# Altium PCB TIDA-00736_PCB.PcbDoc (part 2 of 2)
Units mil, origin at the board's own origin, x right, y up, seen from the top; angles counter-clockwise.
Board outline 3346.46 x 1968.5 mil, 2 copper layers (Top Layer, Bottom Layer), stack 62 mil thick; 81 components, 63 nets, 308 pads, 545 vias.
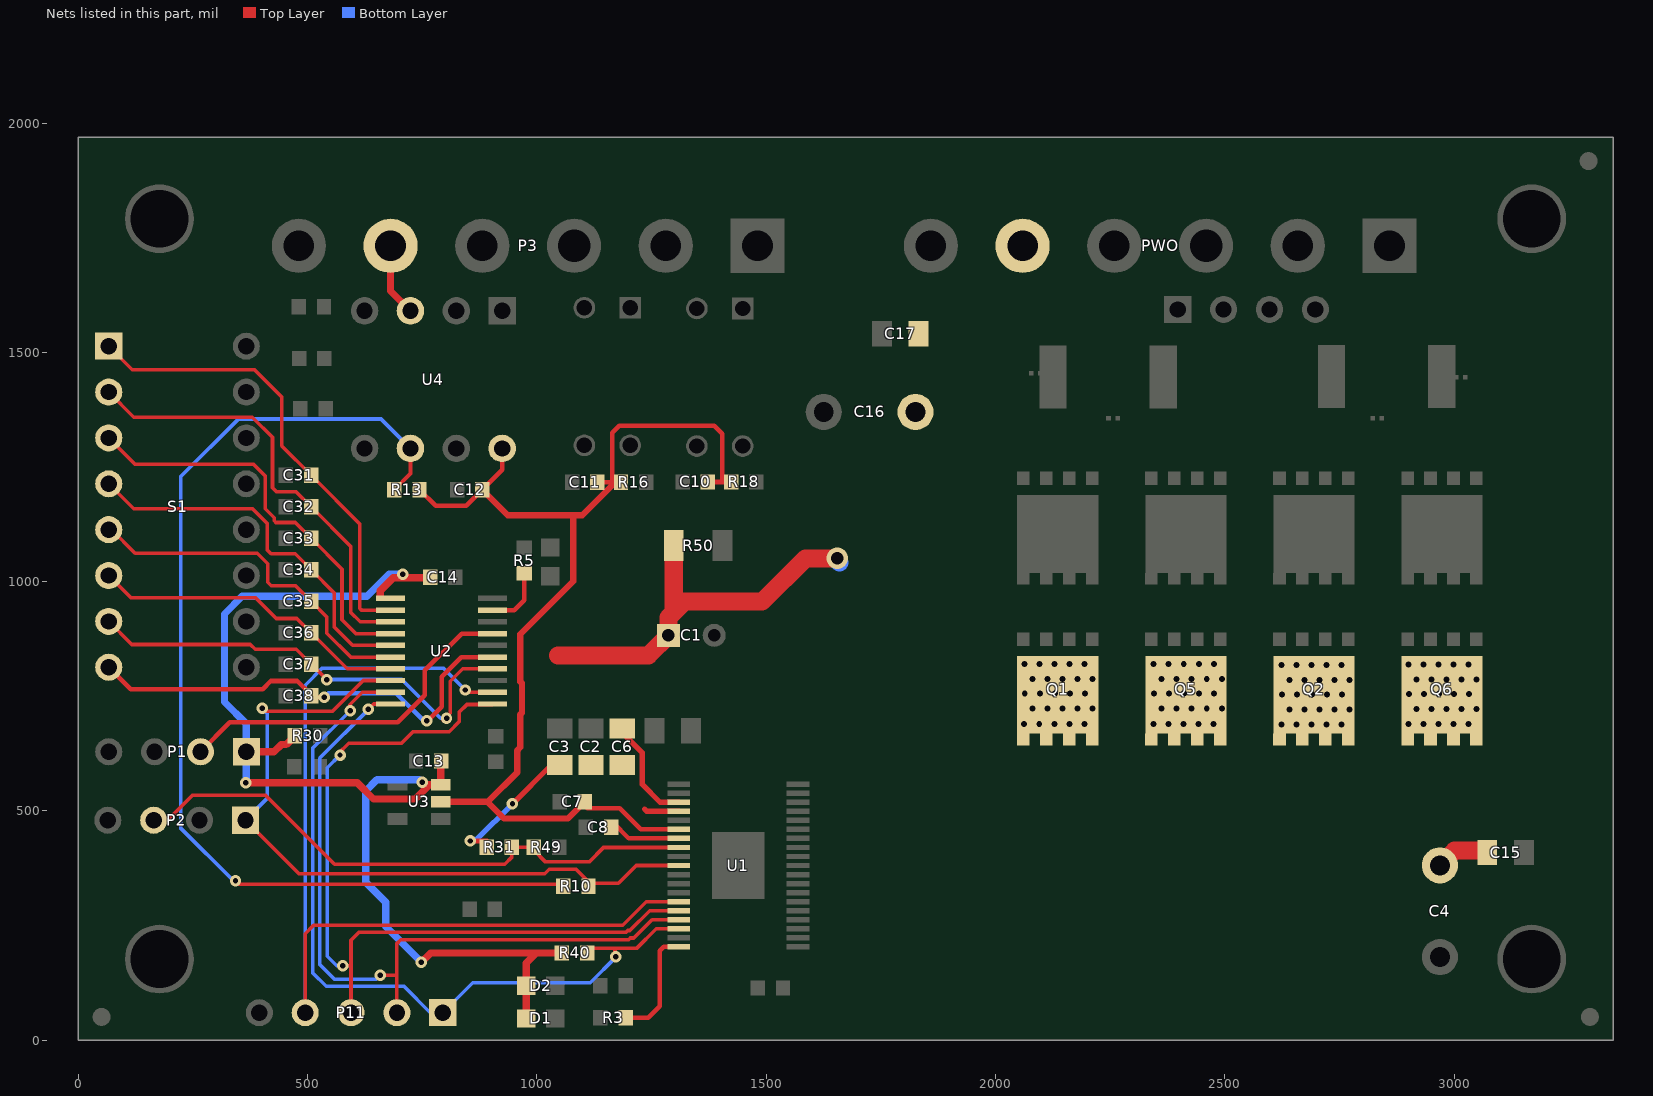
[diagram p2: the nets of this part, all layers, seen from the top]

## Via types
v1: diameter 19.68, hole 13, Top Layer to Bottom Layer, 434 vias
v2: diameter 25, hole 13, Top Layer to Bottom Layer, 54 vias
v3: diameter 25, hole 11.81, Top Layer to Bottom Layer, 17 vias
v4: diameter 25, hole 12, Top Layer to Bottom Layer, 16 vias
v5: diameter 25, hole 15.75, Top Layer to Bottom Layer, 16 vias
v6: diameter 19.68, hole 11.81, Top Layer to Bottom Layer, 7 vias
v7: diameter 47.24, hole 27.56, Top Layer to Bottom Layer, 1 vias

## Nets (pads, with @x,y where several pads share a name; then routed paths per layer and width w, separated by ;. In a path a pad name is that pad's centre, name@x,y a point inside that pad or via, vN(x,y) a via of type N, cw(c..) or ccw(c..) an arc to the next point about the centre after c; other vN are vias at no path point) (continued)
REG3P3: C13.2 C14.2 D1.1 D2.1 P1.1 R30.1 R40.1 U2.1 U3.3 | length 2623.8
  Top Layer w15.75: v4(365.75,561.42) 608.27,561.42 643.7,525.98 734.65,525.98 766.14,557.48 ; P1.1@366.54,629.13 426.92,629.13 442.47,644.69 453.35,644.69 R30.1@472.44,663.78 ; 658.66,970.08 658.66,980.32 687.01,1008.66 766.14,1008.66 C14.2@767.32,1009.84 ; v4(748.43,170.47) 768.5,190.55 999.21,190.55 ; v4(750,562.21) 754.72,557.48 766.14,557.48 ; U3.3@771.26,557.48 766.14,557.48 ; C13.2@790.55,614.57 U3.3@790.55,557.48 766.14,557.48 ; D1.1@977.07,47.74 D2.1@977.07,119 977.07,168.41 999.21,190.55 ; R40.1@1054.72,190.55 999.21,190.55
  Bottom Layer w15.75: v4(365.75,561.42) 366.54,562.21 P1.1@366.54,629.13 366.54,690.16 318.9,737.8 318.9,929.78 357.23,968.11 629.53,968.11 678.35,1016.93 706.3,1016.93 v4(707.48,1015.75) ; v4(748.43,170.47) 670.47,248.43 670.47,301.18 626.77,344.88 626.77,543.7 651.18,568.11 744.1,568.11 v4(750,562.21)
S1: C31.2 S1.1 U2.2 | length 1023.1
  Top Layer w8: S1.1@66.54,1513.39 117.72,1462.21 384.25,1462.21 443.7,1402.76 443.7,1296.06 C31.2@507.87,1231.89 613.78,1125.98 613.78,941.73 617.52,937.99 U2.2@680.91,937.99
S2: C32.2 S1.2 U2.3 | length 970.7
  Top Layer w7.87: S1.2@66.54,1413.39 121.26,1358.66 379.72,1358.66 423.62,1314.76 423.62,1204.73 431.89,1196.46 474.63,1196.46 C32.2@507.87,1163.22 594.49,1076.6 594.49,932.68 614.76,912.4 U2.3@680.91,912.4
S3: C33.2 S1.3 U2.4 | length 901.4
  Top Layer w7.87: S1.3@66.54,1313.39 123.62,1256.3 382.08,1256.3 407.87,1230.51 407.87,1158.92 427.56,1139.23 427.56,1132.68 431.1,1129.13 473.28,1129.13 C33.2@507.87,1094.54 575.2,1027.22 575.2,916.93 605.32,886.81 U2.4@680.91,886.81
S4: C34.2 S1.4 U2.5 | length 837.7
  Top Layer w7.87: S1.4@66.54,1213.39 120.87,1159.06 379.92,1159.06 411.81,1127.17 411.81,1069.29 420.47,1060.63 473.12,1060.63 C34.2@507.87,1025.87 558.27,975.48 558.27,901.18 598.23,861.22 U2.5@680.91,861.22
S5: C35.2 S1.5 U2.6 | length 773.8
  Top Layer w7.87: S1.5@66.54,1113.39 72.84,1113.39 124.02,1062.21 390.16,1062.21 413.39,1038.98 413.39,998.82 420.87,991.34 473.73,991.34 C35.2@507.87,957.2 542.13,922.95 542.13,887.4 593.9,835.63 U2.6@680.91,835.63
S6: C36.2 S1.6 U2.7 | length 698.6
  Top Layer w7.87: S1.6@66.54,1013.39 115.35,964.57 387.01,964.57 431.89,919.69 476.72,919.69 C36.2@507.87,888.53 586.36,810.04 U2.7@680.91,810.04
S7: C37.2 S1.7 U2.14 | length 1029.9
  Top Layer w7.87: S1.7@66.54,913.39 116.93,862.99 375.39,862.99 386.02,852.36 475.37,852.36 C37.2@507.87,819.85 508.49,819.85 v4(541.73,786.61) ; v4(803,702) 801.22,702 795.67,696.45 795.67,698.03 811.02,713.39 811.02,782.68 838.39,810.04 U2.14@903.35,810.04
  Bottom Layer w7.87: v4(541.73,786.61) 705.51,786.61 790.12,702 v4(803,702)
S8: C38.2 S1.8 U2.15 | length 1004.6
  Top Layer w10: S1.8@66.54,813.39 114.17,765.75 401.97,765.75 419.69,783.47 477.95,783.47 507.87,753.54 C38.2@507.87,751.18 511.42,747.64 v4(536.22,747.64) ; v4(760,697) 761.96,697 792.52,727.56 792.52,792.91 835.24,835.63 U2.15@903.35,835.63
  Bottom Layer w10: v4(536.22,747.64) 545.67,757.09 692.91,757.09 753,697 v4(760,697)
SCLK: P11.4 U1.14 U2.12 | length 2175
  Top Layer w7.87: P11.4@494.88,60.24 494.88,232.68 513.2,251 1187.22,251 1238.58,302.36 U1.14@1309.45,302.36 ; v3(843.7,763.78) 848.62,758.86 U2.12@903.35,758.86
  Bottom Layer w7.87: P11.4@494.88,60.24 494.88,774.15 531.66,810.93 796.56,810.93 v3(843.7,763.78)
SCS: P11.2 U1.16 U2.10 | length 1625.1
  Top Layer w7.87: v4(632.87,721.46) 644.69,733.27 U2.10@680.91,733.27 ; v4(658.66,142.13) 694.1,142.13 694.88,141.34 ; P11.2@694.88,60.24 694.88,141.34 ; U1.16@1309.45,262.99 1251.18,262.99 1211.19,223 1203.76,223 1200.27,219.5 703.36,219.5 694.88,211.02 694.88,141.34
  Bottom Layer w7.87: v4(632.87,721.46) 526.77,615.35 526.77,165.35 558.66,133.47 650,133.47 v4(658.66,142.13)
SDATAO: P11.1 R40.2 U1.17 U2.9 | length 1705
  Top Layer w7.87: v3(593.31,718.9) 590.95,721.26 590.95,724.8 592.13,725.98 592.13,731.89 619.09,758.86 U2.9@680.91,758.86 ; R40.2@1110.24,202.68 1112.52,200.39 1170.47,200.39 ; v3(1172.44,181.89) 1170.47,183.86 1170.47,200.39 ; U1.17@1309.45,243.31 1260.24,243.31 1217.32,200.39 1170.47,200.39
  Bottom Layer w7.87: v3(593.31,718.9) 511.02,636.61 511.02,147.64 540.95,117.72 710.24,117.72 767.72,60.24 P11.1@794.88,60.24 860.24,125.59 1116.14,125.59 v3(1172.44,181.89)
SDATI: P11.3 U1.15 U2.11 | length 1810
  Top Layer w7.87: v3(570.87,622.05) 568.9,622.05 566.54,624.41 590.16,648.03 705.03,648.03 730,673 749.62,673 749.93,672.69 770.07,672.69 770.38,673 808.96,673 831.1,695.15 831.1,715.75 847.64,732.28 902.36,732.28 U2.11@903.35,733.27 ; v3(577.17,162.6) 594.88,162.6 ; P11.3@594.88,60.24 594.88,162.6 ; U1.15@1309.45,282.68 1246.06,282.68 1202.76,239.37 1197.86,239.37 1193.74,235.25 611.63,235.25 594.88,218.5 594.88,162.6
  Bottom Layer w7.87: v3(570.87,622.05) 542.91,594.09 542.91,183.07 563.39,162.6 v3(577.17,162.6)
SLEEPN: P2.3 R31.2 R49.1 U1.8 | length 1287.4
  Top Layer w8: P2.3@164.57,479.92 194.47,479.92 248.55,534 409,534 559,384 930,384 945.56,399.56 R31.2@945.56,421 R49.1@993.44,421 993.44,414.56 1019,389 1114,389 1145.47,420.47 U1.8@1309.45,420.47
STALLN: R3.1 U1.19 | length 250.6
  Top Layer w10: R3.1@1193.7,49.21 1242.91,49.21 1268.11,74.41 1268.11,195.28 1276.77,203.94 U1.19@1309.45,203.94
STATE: R5.2 U2.19 | length 125.4
  Top Layer w10: U2.19@903.35,937.99 950.59,937.99 972.44,959.84 R5.2@972.44,1007.09
STEP_AIN1: P2.1 R10.1 U1.10 U2.8 | length 1610.9
  Top Layer w7.87: P2.1@364.57,479.92 481.49,363 1017,363 1027,373 1085.36,373 1116,342.36 1177.8,342.36 1216.54,381.1 U1.10@1309.45,381.1 ; v4(400.79,724.41) 400,723.62 400,717.32 554.53,717.32 621.65,784.45 U2.8@680.91,784.45
  Bottom Layer w7.87: P2.1@364.57,479.92 411.81,527.17 411.81,713.39 v4(400.79,724.41)
STP: P3.5 U4.3 | length 159.7
  Top Layer w15.75: P3.5@681.1,1732.28 681.1,1633.86 U4.3@724.41,1590.55
STP_ISO: R10.2 R13.2 U4.6 | length 2333.7
  Top Layer w7.87: R13.2@688.98,1200.39 724.41,1235.83 U4.6@724.41,1290.55
  Top Layer w8: v3(342.91,347.64) 350.55,340 R10.2@1055.44,340
  Bottom Layer w7.87: v3(342.91,347.64) 338.39,347.64 223.23,462.8 223.23,1228.54 349.41,1354.72 660.24,1354.72 U4.6@724.41,1290.55
TEST: P1.2 U2.17 | length 775.2
  Top Layer w10: P1.2@266.54,629.13 330.79,693.39 696.63,693.39 755.91,752.66 755.91,806.69 836.02,886.81 U2.17@903.35,886.81
V5: C7.1 C10.2 C11.2 C12.2 R13.1 R16.1 R18.1 U1.6 U3.2 U4.8 | length 2456.8
  Top Layer w10: R13.1@744.1,1200.39 779.13,1165.35 846.06,1165.35 C12.2@881.1,1200.39 924.41,1243.7 U4.8@924.41,1290.55 ; C7.1@1110.24,505.91 1180.71,505.91 1226.77,459.84 U1.6@1309.45,459.84 ; C11.2@1131.89,1216.93 1161.81,1216.93 ; R16.1@1183.46,1216.93 1171.26,1216.93 1164.35,1216.93 ; C10.2@1372.83,1217.32 1403.94,1217.32 ; R18.1@1423.62,1217.32 1403.94,1217.32 ; 1161.81,1216.93 1164.35,1216.93 ; 1161.81,1216.93 1164.35,1214.39 1164.35,1216.93 ; 1164.35,1216.93 1164.35,1324.59 1179.53,1339.76 1387.01,1339.76 1403.94,1322.84 1403.94,1217.32
  Top Layer w13.78: U3.2@790.55,520.08 892.13,520.08 928.74,483.47 1067.72,483.47 C7.1@1104.73,520.47 ; C12.2@881.1,1200.39 936.61,1144.88 1079.53,1144.88 ; 895,522 957,584 957,632 964,639 964,688.61 964,710.36 967.48,713.84 967.48,778.28 964,781.76 964,790.85 964,885.39 1079.53,1000.92 1079.53,1144.88 ; R16.1@1171.26,1216.93 1099.21,1144.88 1079.53,1144.88
VCP: C6.1 U1.3 | length 248
  Top Layer w11.81: C6.1@1174.41,687.24 1174.41,682.28 1229.53,627.17 1229.53,558.41 1269.04,518.9 U1.3@1309.45,518.9
VINT: C8.1 U1.7 | length 156.9
  Top Layer w10: C8.1@1166.54,474.02 1200.39,440.16 U1.7@1309.45,440.16
VM: C1.1 C2.1 C3.1 C4.1 C6.2 C15.2 C16.1 C17.2 PWO.5 Q1.5 Q2.5 Q5.5 Q6.5 R31.1 R50.1 U1.4 | length 1373.5
  Top Layer w11.81: v3(854.72,434.65) R31.1@891.34,434.65 ; v3(946.85,515.75) 1030.87,599.76 C3.1@1054.33,599.76 ; 1234.65,504.33 1239.76,499.21 U1.4@1309.45,499.21
  Top Layer w39.37: 1045.67,839.37 1242.91,839.37 C1.1@1286.61,883.07 1286.61,921.65 1303.15,938.19 ; R50.1@1298.43,1078.74 1298.43,942.91 1303.15,938.19 ; v7(1654.72,1050.79) 1585.43,1050.79 1491.34,956.69 1321.65,956.69 1303.15,938.19 ; C4.1@2968.9,381.5 3001.18,413.78 3001.18,414.17 3067.48,414.17 C15.2@3072.21,409.45
  Bottom Layer w11.81: v3(854.72,434.65) 854.72,435.04 857.09,437.4 868.5,437.4 v3(946.85,515.75)
  Bottom Layer w39.37: v7(1654.72,1050.79) 1654.72,1046.46 v7@1659.45,1041.73
  other v1: 2623.23,688.19 2656.01,688.19 2688.78,688.19 2721.56,688.19 2754.33,688.19 2900,689.37 2932.78,689.37 2965.55,689.37 2998.33,689.37 3031.1,689.37 2062.6,690.16 2095.38,690.16 2128.15,690.16 2160.93,690.16 2193.7,690.16 2344.49,690.16 2377.27,690.16 2410.04,690.16 2442.82,690.16 2475.59,690.16 2640.95,721.26 2673.72,721.26 2706.5,721.26 2739.27,721.26 2772.05,721.26 2917.72,722.44 2950.49,722.44 2983.27,722.44 3016.04,722.44 3048.82,722.44 2080.32,723.23 2113.09,723.23 2145.87,723.23 2178.64,723.23 2211.42,723.23 2362.21,723.23 2394.98,723.23 2427.76,723.23 2460.53,723.23 2493.31,723.23 2624.41,753.94 2657.19,753.94 2689.96,753.94 2722.74,753.94 2755.51,753.94 2063.78,755.91 2096.56,755.91 2129.33,755.91 2162.11,755.91 2194.88,755.91 2345.67,755.91 2378.45,755.91 2411.22,755.91 2444,755.91 2476.77,755.91 2901.18,755.12 2933.96,755.12 2966.73,755.12 2999.51,755.12 3032.28,755.12 2640.95,785.83 2673.72,785.83 2706.5,785.83 2739.27,785.83 2772.05,785.83 2917.72,787.01 2950.49,787.01 2983.27,787.01 3016.04,787.01 3048.82,787.01 2080.32,787.8 2113.09,787.8 2145.87,787.8 2178.64,787.8 2211.42,787.8 2362.21,787.8 2394.98,787.8 2427.76,787.8 2460.53,787.8 2493.31,787.8 2623.62,818.5 2656.4,818.5 2689.17,818.5 2721.95,818.5 2754.72,818.5 2900.39,819.69 2933.17,819.69 2965.95,819.69 2998.72,819.69 3031.5,819.69 2062.99,820.47 2095.77,820.47 2128.54,820.47 2161.32,820.47 2194.1,820.47 2344.88,820.47 2377.66,820.47 2410.43,820.47 2443.21,820.47 2475.98,820.47
pads on no net: FID1.1 FID2.1 FID3.1 U1.12 U1.13 U3.4 U3.5 U4.1 U4.4 U4.7

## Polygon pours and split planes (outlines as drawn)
GND on Top Layer "Bottom Layer-No Net" (solid, remove dead copper, pour order 47): 3,1975 3349.46,1975 3349.46,6.5 3,6.5
VM on Top Layer "Bottom Layer-No Net" (solid, remove dead copper, pour order 43): 998.82,552.76 955.12,484.65 928.74,483.47 886.61,518.9 892.13,652.76 952.36,712.99 952.36,873.75 1079.53,1000.92 1326.77,1001.18 1326.77,826.77 1169.69,777.17 1030.71,777.17 1030.87,599.76
GND on Top Layer "Bottom Layer-No Net" (solid, remove dead copper, pour order 41): 1024.8,659.06 1024.8,767.72 1187.4,768.9 1182.68,716.93 1148.43,659.06
VM on Top Layer "Bottom Layer-No Net" (solid, remove dead copper, pour order 37): 1967.32,1798.03 2162.6,1795.67 2018.11,1492.13 1829.53,1308.27 1744.49,1361.02 1852.36,1600 1955.91,1777.17
NetJJ1_2 on Top Layer "Bottom Layer-No Net" (solid, remove dead copper, pour order 23): 2563.78,1539.37 2561.42,1537.01 2245.67,1537.01 2245.67,1360.63 2238.58,1353.54 2237.4,1354.72 1994.1,1354.72 1994.1,1212.21 1996.06,1210.24 1998.82,1207.48 2563.39,1207.48
NetJJ2_2 on Top Layer "Bottom Layer-No Net" (solid, remove dead copper, pour order 21): 2563.78,1208.66 3094.49,1208.66 3094.49,1353.15 3091.73,1355.91 2850.79,1355.91 2850.79,1518.9 2833.86,1535.83 2830.32,1539.37 2563.78,1539.37
BOUT2 on Top Layer "Bottom Layer-No Net" (solid, remove dead copper, pour order 9): 2829.13,1188.98 3138.58,1188.98 3139.37,1189.76 3139.37,857.48 2829.13,857.48
BOUT1 on Top Layer "Bottom Layer-No Net" (solid, remove dead copper, pour order 7): 2574.31,1188.98 2827.17,1188.98 2827.17,857.48 2828.35,856.3 2827.17,857.48 2572.84,857.48
AOUT2 on Top Layer "Bottom Layer-No Net" (solid, remove dead copper, pour order 5): 2274.8,1190.95 2573.13,1190.95 2574.31,1192.13 2574.31,858.66 2279.13,858.66 2275.98,861.81
AOUT1 on Top Layer "Bottom Layer-No Net" (solid, remove dead copper, pour order 3): 1962.99,1189.76 2274.02,1189.76 2274.02,859.84 2272.05,861.81 1962.99,861.81
VM on Top Layer "Bottom Layer-No Net" (solid, remove dead copper, pour order 2): 988.19,622.44 988.58,622.84 1215.35,622.84 1215.35,544.88 1259.45,500.79 1266.14,494.09 1266.54,494.09 1266.54,492.91 1254.33,480.71 1251.18,477.56 1234.25,477.56 1233.07,477.56 1189.76,520.87 1189.37,520.87 1175.98,534.25 1175.59,534.25 1159.84,550 1157.09,552.76 1029.92,552.76 998.82,552.76 988.19,563.39
GND on Bottom Layer "GND" (solid, remove dead copper, pour order 45): 0,1968.5 0,0 3346.46,0 3346.46,1968.5
VM on Bottom Layer "Bottom Layer-No Net" (solid, remove dead copper, pour order 35): 3151.18,572.84 3118.9,370.47 2925.98,285.43 2856.69,340.55 2824.8,471.65 2045.67,556.69 2045.67,575.2
VM on Bottom Layer "Bottom Layer-No Net" (solid, remove dead copper, pour order 33): 1964.96,1807.09 2178.74,1807.09 1981.1,1037.01 2227.17,954.33 2939.76,974.8 3118.9,1066.93 3151.18,1048.43 3151.18,561.42 2045.67,561.42 2024.8,674.02 1866.14,701.58 1721.26,804.72 1638.58,1064.57 1728.35,1448.43
BOUT2 on Bottom Layer "Bottom Layer-No Net" (solid, remove dead copper, pour order 31): 2768.5,1807.48 2931.89,1805.51 3137.01,1059.06 2892.54,932.18 2635.83,1617.32
BOUT1 on Bottom Layer "Bottom Layer-No Net" (solid, remove dead copper, pour order 29): 2551.97,1807.48 2759.06,1811.02 2751.58,1722.05 2664.17,1611.81 2662.21,1556.69 2894.1,927.95 2557.87,941.34
AOUT2 on Bottom Layer "Bottom Layer-No Net" (solid, remove dead copper, pour order 27): 2356.3,1809.45 2540.55,1809.45 2544.49,1636.61 2548.43,943.31 2191.34,929.92
AOUT1 on Bottom Layer "Bottom Layer-No Net" (solid, remove dead copper, pour order 25): 2191.34,1803.54 2193.31,1805.51 2318.5,1805.51 2327.95,1805.51 2331.89,1801.58 2430.71,1615.75 2430.71,1556.69 2175.98,916.54 1951.97,1034.25

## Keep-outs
Keep-Out Layer:
  lines w3.94: 3.15,98.43 103.15,98.43 103.15,-1.57 ; 3243.31,1970.08 3243.31,1870.08 3343.31,1870.08 ; 3248.03,3.15 3248.03,103.15 3348.03,103.15
  lines w6.69: 1112,1003.73 1112,1111 1167.54,1166.54 1497.64,1166.54 1558.27,1227.17 1558.27,1968.5
  lines w8: 0,0 3346.46,0 3346.46,1968.5 0,1968.5 0,0
  text ".Layer_Name" at 295.35,-1258.89 h60

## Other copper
Top Layer:
  text ".Layer_Name" at 295.35,-1258.89 h60
Bottom Layer:
  text ".Layer_Name" at 295.35,-1258.89 h60

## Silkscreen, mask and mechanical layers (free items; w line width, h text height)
Top Overlay:
  text "A+" at 2785.43,1570.47 h31.5
  text "A-" at 2873.49,1570.47 h31.5
  text "B+" at 2961.55,1570.47 h31.5
  text "B-" at 3049.61,1570.47 h31.5
  text "VM+" at 2081.1,1551.18 h31.5 r90
  text ".PCB_Rev" at 3310,1135 h60 r90
  text "SBW" at 179.13,538.98 h31.5
  text ".PRJ_Number" at 3310,535 h60 r90
  text "E  D  S" at 159.84,384.25 h31.5
  text "FAULTn" at 836.22,180.71 h31.5
  text "SI" at 604.33,122.05 h31.5 r45
  text "GD" at 387.01,120.47 h31.5 r45
  text "SC" at 492.13,120.47 h31.5 r45
  text "SS" at 699.61,119.29 h31.5 r45
  text "SO" at 800.79,119.29 h31.5 r45
  text "STALLn" at 1310.24,24.8 h31.5
  text ".Layer_Name" at 295.35,-1258.89 h60
Bottom Overlay:
  text ".Layer_Name" at 295.35,-1258.89 h60
Top Paste:
  text ".Layer_Name" at 295.35,-1258.89 h60
Bottom Paste:
  text ".Layer_Name" at 295.35,-1258.89 h60
Top Solder:
  text ".Layer_Name" at 295.35,-1258.89 h60
  text ".Layer_Name" at 295.35,-1258.89 h60
Bottom Solder:
  text ".Layer_Name" at 295.35,-1258.89 h60
Drill Guide:
  text ".Layer_Name" at 295.35,-1258.89 h60
M1 Board Outline:
  the board outline again, w8
  text ".Layer_Name" at 295.35,-1258.89 h60
M2 Board Dimensions:
  rectangle: 124.35,-325.39 499.35,-200.39
  rectangle: -0.65,-200.39 124.35,-75.39
  lines w7: -0.65,-200.39 999.35,-200.39 ; 124.35,-325.39 124.35,-75.39 ; 249.35,-325.39 249.35,-75.39 ; 499.35,-325.39 499.35,-75.39 ; 749.35,-325.39 749.35,-75.39 ; -0.65,-325.39 -0.65,-75.39 999.35,-75.39 999.35,-325.39 -0.65,-325.39
  text ".Layer_Name" at 295.35,-1258.89 h60
M3 3D STEP Top:
  text ".Layer_Name" at 295.35,-1258.89 h60
M4 3D STEP Bottom:
  text ".Layer_Name" at 295.35,-1258.89 h60
M5 Assembly Top:
  lines w10: -573.65,-1330.56 6026.35,-1330.56 ; -573.65,-1127.23 6028.35,-1127.23 ; -573.65,-923.89 -573.65,-1533.89 3431.35,-1533.89 6028.35,-1533.89 6028.35,-923.89 -573.15,-923.89 -573.15,-1533.89 1002.35,-1533.89 ; 1891.35,-1533.89 1891.35,-923.89 ; 3158.35,-1127.23 3158.35,-923.89 ; 3998.35,-1127.23 3998.35,-923.89 ; 4620.35,-1540.39 4620.35,-1337.56
  text "COMPONENTS MARKED 'DNP' SHOULD NOT BE POPULATED." at 871.85,-718.89 h60
  text "ASSEMBLY VARIANT:" at 871.35,-834.39 h60
  text ".VariantName" at 1907.35,-834.39 h60
  text "PCB VIEWED FROM TOP SIDE" at -510.15,-1056.06 h60
  text "BOARD #:" at 1966.35,-1056.06 h60
  text ".PRJ_Number" at 2511.85,-1056.06 h60
  text "REV:" at 3356.35,-1056.06 h60
  text ".PCB_Rev" at 3647.85,-1056.06 h60
  text "SVN REV:" at 4194.35,-1056.06 h60
  text ".VersionControl_RevNumber" at 4700.35,-1056.06 h60
  text "TID #:" at 1966.35,-1259.39 h60
  text ".TID" at 2511.85,-1259.39 h60
  text "PLOT NAME =" at -510.15,-1464.73 h60
  text ".plot_File_Name" at 295.35,-1464.73 h60
  text "GENERATED    :" at 1968.35,-1464.73 h60
  text ".Print_Date" at 2837.85,-1464.73 h60
  text ".Print_Time" at 3566.85,-1464.73 h60
  text "TEXAS INSTRUMENTS" at 4831.35,-1464.73 h60
M6 Assembly Bottom:
  lines w10: -574.15,-1127.73 6027.85,-1127.73 ; -572.15,-1331.06 6027.85,-1331.06 ; 833.85,-1540.89 833.85,-1338.06 ; 1455.85,-1127.73 1455.85,-924.39 ; 2295.85,-1127.73 2295.85,-924.39 ; 3562.85,-1534.39 3562.85,-924.39 ; 4451.85,-1534.39 6027.35,-1534.39 6027.35,-924.39 -574.15,-924.39 -574.15,-1534.39 2022.85,-1534.39 6027.85,-1534.39 6027.85,-924.39
  text "COMPONENTS MARKED 'DNP' SHOULD NOT BE POPULATED." at 5820.35,-718.39 h60
  text ".VariantName" at 4776.35,-834.39 h60
  text "ASSEMBLY VARIANT:" at 5815.35,-834.39 h60
  text ".VersionControl_RevNumber" at 753.85,-1056.56 h60
  text "SVN REV:" at 1259.85,-1056.56 h60
  text ".PCB_Rev" at 1806.35,-1056.56 h60
  text "REV:" at 2097.85,-1056.56 h60
  text ".PRJ_Number" at 2942.35,-1056.56 h60
  text "BOARD #:" at 3487.85,-1056.56 h60
  text "PCB VIEWED FROM BOTTOM SIDE" at 5964.35,-1056.56 h60
  text ".TID" at 2942.35,-1259.89 h60
  text "TID #:" at 3487.85,-1259.89 h60
  text "TEXAS INSTRUMENTS" at 622.85,-1465.23 h60
  text ".Print_Time" at 1887.35,-1465.23 h60
  text ".Print_Date" at 2616.35,-1465.23 h60
  text "GENERATED    :" at 3485.85,-1465.23 h60
  text ".plot_File_Name" at 5158.85,-1465.23 h60
  text "PLOT NAME =" at 5964.35,-1465.23 h60
M9 Title Sheet:
  drawing of 57 lines, arcs and shapes, not listed
  text "1" at 458.18,7636.11 h70
  text "2" at 2953.85,7636.11 h70
  text "3" at 5443.19,7636.11 h70
  text "4" at 7949.86,7636.11 h70
  text "5" at 10448.85,7636.11 h70
  text "6" at 12953.85,7636.11 h70
  text "A" at -698.15,6493.11 h70
  text "A" at 14101.85,6493.11 h70
  text "B" at -698.15,4113.11 h70
  text "B" at 14101.85,4113.11 h70
  text "C" at -698.15,1738.11 h70
  text "C" at 14101.85,1738.11 h70
  text "PROJECT TITLE:" at 11061.85,-122.89 h45
  text ".PRJ_Title" at 11111.85,-256.22 h70
  text "DESIGNED FOR:" at 11061.85,-423.89 h45
  text ".PRJ_Customer" at 11111.85,-563.89 h70
  text "D" at -698.15,-631.89 h70
  text "D" at 14101.85,-631.89 h70
  text "FILE NAME:" at 11061.85,-723.89 h45
  text ".PCB_File_Name_No_Path" at 11111.85,-843.89 h70
  text "Texas Instruments (TI) and/or its licensors do not warrant the accuracy or completeness of this specification" at 6092.35,-1005.73 h45
  text "ENGINEER:" at 11061.85,-1013.89 h45
  text "LAYOUT BY:" at 12566.85,-1013.89 h45
  text "or any information contained therein. TI and/or its licensors do not warrant that this design will meet" at 6047.36,-1118.4 h45
  text ".PRJ_Engineer" at 11111.85,-1168.89 h70
  text ".PCB_Layout" at 12617.35,-1168.89 h70
  text "the specifications, will be suitable for your application or fit for any particular purpose, or will operate in" at 6047.36,-1231.06 h45
  text ".Layer_Name" at 295.35,-1258.89 h60
  text "ALTIUM DESIGNER VERSION:" at 12566.85,-1323.89 h45
  text "an implementation. TI and/or its licensors do not warrant that the design is production worthy. You should" at 6047.36,-1343.73 h45
  text "completely validate and test your design implementation to confirm the system functionality for your application." at 6092.35,-1456.39 h45
  text ".print_Scale" at 11111.85,-1457.22 h70
  text ".Application_BuildNumber" at 12617.35,-1457.22 h70
  text "1" at 458.18,-1663.89 h70
  text "2" at 2953.85,-1663.89 h70
  text "3" at 5443.19,-1663.89 h70
  text "4" at 7949.86,-1663.89 h70
  text "5" at 10448.85,-1663.89 h70
  text "6" at 12953.85,-1663.89 h70
M10 Fab Notes:
  drawing of 189 lines, arcs and shapes, not listed
  text "DESIGN INFORMATION" at 12099.37,5627.61 h60
  text "MIN. TRACK WIDTH:" at 11454.81,5447.61 h60
  text "8" at 12551.05,5447.61 h60
  text "MIL" at 12705.81,5447.61 h60
  text "MIN. CLEARANCE:" at 11454.81,5315.61 h60
  text "0.2" at 12491.05,5315.61 h60
  text "mm" at 12705.81,5315.61 h60
  text "MIN. VIA PAD SIZE:" at 11454.81,5183.61 h60
  text "24" at 12521.06,5183.61 h60
  text "MIL" at 12705.81,5183.61 h60
  text "0.05mm (2MIL)" at 12149.81,5041.9 h60
  text "MINIMUM ANNULAR RING" at 11125.57,5037.61 h60
  text "EXTERNAL" at 12857.81,5037.61 h60
  text "PER" at 11325.57,4919.61 h60
  text "IPC-D-275 CLASS 2 LEVEL C" at 11545.57,4919.61 h60
  text "MIL, HOLES" at 13033.81,4807.32 h60
  text "+/-" at 12641.35,4806.61 h60
  text "+/-" at 13495.35,4806.61 h60
  text "REGISTRATION TOLERANCES:" at 11125.57,4801.61 h60
  text "METAL" at 12325.35,4801.61 h60
  text "5" at 12901.55,4801.61 h60
  text "3" at 13734.55,4801.61 h60
  text "MIL" at 13850.81,4801.61 h60
  text "+/-" at 13495.35,4688.61 h60
  text "HOLE SIZE TOLERANCE (UNLESS OTHERWISE SPECIFIED):" at 11125.57,4683.61 h60
  text "3" at 13734.55,4683.61 h60
  text "MIL" at 13850.81,4683.61 h60
  text "MATERIAL:" at 11050.81,4474.15 h60
  text "FR-4 High Tg" at 12037.25,4333.81 h60
  text "FR-408" at 11471.81,4325.24 h60
  text "OTHER" at 12959.81,4325.24 h60
  text "X" at 11882.35,4321.61 h60
  text "62 MIL (1.6mm) +/-10%" at 11791.91,4162.53 h60
  text "THICKNESS:" at 11125.57,4158.25 h60
  text "X" at 11663.74,4158.25 h60
  text "OTHER" at 13076.81,4158.25 h60
  text "TOLERANCE:" at 11125.57,4000.25 h60
  text "X" at 11964.88,4000.25 h60
  text "ANSI IPC-6012 TYPE 3 CLASS 2" at 12151.82,4000.25 h60
  text "OTHER +/-" at 12151.81,3844.25 h60
  text "BOW & TWIST:" at 11125.57,3687.25 h60
  text "X" at 11964.88,3687.25 h60
  text "ANSI IPC-6012 TYPE 3 CLASS 2" at 12151.82,3687.25 h60
  text "OTHER +/-" at 12151.81,3528.74 h60
  text "DRILLING:" at 11050.81,3390.25 h60
  text "REFERENCE:" at 11125.57,3273.25 h60
  text "X" at 11773.81,3273.25 h60
  text "AS SHOWN" at 11960.81,3273.25 h60
  text "X" at 12674.81,3273.25 h60
  text "NC_DRILL FILES" at 12811.81,3273.25 h60
  text "PTH MIN COPPER THICKNESS:" at 11125.57,3115.25 h60
  text "X" at 12475.81,3115.25 h60
  text "1MIL" at 12612.81,3115.25 h60
  text "OTHER" at 13109.81,3115.25 h60
  text "BOARD FINISH:" at 11050.81,2956.25 h60
  text "SILKSCREEN:" at 11206.03,2838.25 h60
  text "X" at 12154.81,2838.25 h60
  text "TOP" at 12280.81,2838.25 h60
  text "X" at 12664.81,2838.25 h60
  text "BOTTOM" at 12791.81,2838.25 h60
  text "SILKSCREEN COLOR:" at 11206.03,2671.25 h60
  text "X" at 12153.77,2671.25 h60
  text "WHITE" at 12280.81,2671.25 h60
  text "OTHER" at 12791.81,2671.25 h60
  text "X" at 12284.77,2512.05 h60
  text "GREEN" at 12411.81,2512.05 h60
  text "OTHER" at 13029.81,2512.05 h60
  text "SOLDER RESIST COLOR:" at 11206.03,2501.25 h60
  text "X" at 12284.77,2342.05 h60
  text "MATTE" at 12411.81,2342.05 h60
  text "SEMI-GLOSS" at 13029.35,2341.41 h60
  text "IMMERSION GOLD (ENIG)" at 12111.81,2153.53 h60
  text "ENEPIG" at 13449.35,2150.25 h60
  text "SURFACE FINISH:" at 11050.81,2149.25 h60
  text "X" at 11924.86,2149.25 h60
  text "IMM. TIN/SILVER OR EQUIV" at 11380.35,1992.25 h60
  text "OTHER" at 12811.81,1992.25 h60
  text "ARRAY/PANEL:" at 11050.81,1813.25 h60
  text "CUT AND TRIM PER M1 BOARD OUTLINE" at 12111.81,1808.96 h60
  text "N.C. ROUTE" at 12111.81,1657.25 h60
  text "X" at 12790.81,1657.25 h60
  text "V. SCORE" at 12977.81,1657.25 h60
  text "CERTIFICATION:" at 11050.81,1520.25 h60
  text "MATERIALS AND WORKMANSHIP FOR ALL PCBS" at 11775.81,1520.25 h60
  text "TO MEET OR EXCEED THE REQUIREMENTS OF:" at 11775.81,1422.25 h60
  text "X" at 11402.31,1285.74 h60
  text "ANSI IPC-A-600F CLASS ->" at 11541.31,1285.74 h60
  text "X" at 13180.36,1285.74 h60
  text "2" at 13299.31,1285.74 h60
  text "1" at 12984.31,1284.25 h60
  text "3" at 13653.31,1284.24 h60
  text "X" at 11404.36,1126.25 h60
  text "UL 94V-0" at 11541.31,1126.25 h60
  text "X" at 12216.36,1126.25 h60
  text "RoHS" at 12353.31,1126.25 h60
  text "OTHER" at 12997.71,1126.25 h60
  text "PER ORDER" at 13394.77,1126.25 h60
  text "ADDITIONAL REQUIREMENTS:" at 11050.81,985.25 h60
  text "MICROSECTION:" at 11125.57,870.25 h60
  text "YES" at 12031.31,870.25 h60
  text "REQUIRED" at 12892.81,714.1 h60
  text "BARE BOARD ELEC. TEST:" at 11125.57,711.24 h60
  text "NONE" at 12431.31,711.24 h60
  text "X" at 12765.81,711.24 h60
  text "PER ORDER" at 13484.81,711.24 h60
  text "MANUFACTURER'S UL:" at 11125.57,554.25 h60
  text "RAIL" at 12291.31,549.96 h60
  text "METAL" at 12783.12,549.96 h60
  text "X" at 13158.35,549.61 h60
  text "SILK" at 13294.81,549.96 h60
  text ".Layer_Name" at 295.35,-1258.89 h60
M11 Gerber Information:
  lines w10: -573.65,-1330.56 6026.35,-1330.56 ; -573.65,-1127.23 6028.35,-1127.23 ; -573.65,-923.89 -573.65,-1533.89 3431.35,-1533.89 6028.35,-1533.89 6028.35,-923.89 -573.15,-923.89 -573.15,-1533.89 1002.35,-1533.89 ; 1891.35,-1533.89 1891.35,-923.89 ; 3158.35,-1127.23 3158.35,-923.89 ; 3998.35,-1127.23 3998.35,-923.89 ; 4620.35,-1540.39 4620.35,-1337.56
  text "ALL ARTWORK VIEWED FROM TOP SIDE" at -510.15,-1056.06 h60
  text "BOARD #:" at 1966.35,-1056.06 h60
  text ".PRJ_Number" at 2511.85,-1056.06 h60
  text "REV:" at 3356.35,-1056.06 h60
  text ".PCB_Rev" at 3647.85,-1056.06 h60
  text "SVN REV:" at 4194.35,-1056.06 h60
  text ".VersionControl_RevNumber" at 4700.35,-1056.06 h60
  text "LAYER NAME =" at -510.15,-1258.89 h60
  text "TID #:" at 1966.35,-1259.39 h60
  text ".TID" at 2511.85,-1259.39 h60
  text "PLOT NAME =" at -510.15,-1464.73 h60
  text ".plot_File_Name" at 295.35,-1464.73 h60
  text "GENERATED    :" at 1968.35,-1464.73 h60
  text ".Print_Date" at 2837.85,-1464.73 h60
  text ".Print_Time" at 3566.85,-1464.73 h60
  text "TEXAS INSTRUMENTS" at 4831.35,-1464.73 h60
M12 Stackup:
  drawing of 191 lines, arcs and shapes, not listed
  text "Layer" at 9508.92,7429.61 h60
  text "Name" at 9918.84,7429.61 h60
  text "Material" at 10848.58,7429.61 h60
  text "Thickness" at 11708.35,7429.61 h60
  text "Constant" at 12358.18,7429.61 h60
  text "Board Layer Stack" at 12928.04,7429.61 h60
  text "1" at 9508.92,7309.61 h60
  text "Top Overlay" at 9918.84,7309.61 h60
  text "2" at 9508.92,7189.61 h60
  text "Top Solder" at 9918.84,7189.61 h60
  text "Solder Resist" at 10848.58,7189.61 h60
  text "0.40mil" at 11708.35,7189.61 h60
  text "3.5" at 12358.18,7189.61 h60
  text "3" at 9508.92,7069.61 h60
  text "Top Layer" at 9918.84,7069.61 h60
  text "Copper" at 10848.58,7069.61 h60
  text "1.40mil" at 11708.35,7069.61 h60
  text "4" at 9508.92,6949.61 h60
  text "Dielectric1" at 9918.84,6949.61 h60
  text "FR-4" at 10848.58,6949.61 h60
  text "59.20mil" at 11708.35,6949.61 h60
  text "4.8" at 12358.18,6949.61 h60
  text "5" at 9508.92,6829.61 h60
  text "Bottom Layer" at 9918.84,6829.61 h60
  text "Copper" at 10848.58,6829.61 h60
  text "1.40mil" at 11708.35,6829.61 h60
  text "6" at 9508.92,6709.61 h60
  text "Bottom Solder" at 9918.84,6709.61 h60
  text "Solder Resist" at 10848.58,6709.61 h60
  text "0.40mil" at 11708.35,6709.61 h60
  text "3.5" at 12358.18,6709.61 h60
  text "7" at 9508.92,6589.61 h60
  text "Bottom Overlay" at 9918.84,6589.61 h60
  text ".Layer_Name" at 295.35,-1258.89 h60
M13 Component Bodies Top:
  text ".Layer_Name" at 295.35,-1258.89 h60
M14 Component Bodies Bottom:
  text ".Layer_Name" at 295.35,-1258.89 h60
M15 Courtyards Top:
  text ".Layer_Name" at 295.35,-1258.89 h60
M16 Courtyards Bottom:
  text ".Layer_Name" at 295.35,-1258.89 h60
Drill Drawing:
  circle w3.33: c5291.15,2820.44 r24.91
  circle w3.33: c5291.15,1624.77 r14.95
  circle w3.33: c5291.15,1624.77 r24.91
  lines w3.33: 5266.24,1151.48 5316.06,1151.48 5316.06,1201.3 5266.24,1201.3 5266.24,1151.48 ; 5266.24,1313.39 5278.69,1313.39 5291.15,1300.94 5303.6,1313.39 5316.06,1313.39 5303.6,1325.85 5316.06,1338.3 5303.6,1338.3 5291.15,1350.76 5278.69,1338.3 5266.24,1338.3 5278.69,1325.85 5266.24,1313.39 ; 5266.24,1500.22 5316.06,1500.22 5291.15,1450.4 5266.24,1500.22 ; 5266.24,1749.32 5316.06,1749.32 5316.06,1799.14 5266.24,1799.14 5266.24,1749.32 ; 5266.24,1923.68 5291.15,1898.77 5316.06,1923.68 5291.15,1948.59 5266.24,1923.68 ; 5266.24,2048.23 5266.24,2060.69 5278.69,2073.14 5266.24,2085.6 5266.24,2098.05 5278.69,2098.05 5291.15,2085.6 5303.6,2098.05 5316.06,2098.05 5316.06,2085.6 5303.6,2073.14 5316.06,2060.69 5316.06,2048.23 5303.6,2048.23 5291.15,2060.69 5278.69,2048.23 5266.24,2048.23 ; 5266.24,2210.15 5278.69,2210.15 5278.69,2197.69 5303.6,2197.69 5303.6,2210.15 5316.06,2210.15 5316.06,2235.06 5303.6,2235.06 5303.6,2247.51 5278.69,2247.51 5278.69,2235.06 5266.24,2235.06 5266.24,2210.15 ; 5266.24,2347.15 5291.15,2359.61 5316.06,2347.15 5303.6,2372.06 5316.06,2396.97 5291.15,2384.52 5266.24,2396.97 5278.69,2372.06 5266.24,2347.15 ; 5266.24,2509.06 5278.69,2509.06 5291.15,2496.61 5303.6,2509.06 5316.06,2509.06 5303.6,2521.52 5316.06,2533.97 5303.6,2533.97 5291.15,2546.43 5278.69,2533.97 5266.24,2533.97 5278.69,2521.52 5266.24,2509.06 ; 5266.24,2695.89 5316.06,2695.89 5291.15,2646.07 5266.24,2695.89 ; 5276.2,1318.38 5283.67,1318.38 5291.15,1310.9 5298.62,1318.38 5306.09,1318.38 5298.62,1325.85 5306.09,1333.32 5298.62,1333.32 5291.15,1340.8 5283.67,1333.32 5276.2,1333.32 5283.67,1325.85 5276.2,1318.38 ; 5276.2,1490.25 5306.09,1490.25 5291.15,1460.36 5276.2,1490.25 ; 5276.2,1759.28 5306.09,1759.28 5306.09,1789.17 5276.2,1789.17 5276.2,1759.28
  lines w12: 5198.35,1106.64 7317.74,1106.64 ; 5198.35,2900.15 7317.74,2900.15 ; 5569.01,957.18 5569.01,3049.61 ; 5926.13,957.18 5926.13,3049.61 ; 6588.13,957.18 6588.13,3049.61 ; 6872.49,957.18 6872.49,3049.61 ; 5198.35,957.18 7317.74,957.18 7317.74,3049.61 5198.35,3049.61 5198.35,957.18
  text "Symbol" at 5288.02,2944.99 h72
  text "Quantity" at 5613.85,2944.99 h72
  text "Finished Hole Size" at 5970.97,2944.99 h72
  text "Plated" at 6632.97,2944.99 h72
  text "Hole Type" at 6917.32,2944.99 h72
  text "24" at 5613.85,2795.53 h60
  text "11.81mil (0.300mm)" at 5970.97,2795.53 h60
  text "PTH" at 6632.97,2795.53 h60
  text "Round" at 6917.32,2795.53 h60
  text "16" at 5613.85,2646.07 h60
  text "12.00mil (0.305mm)" at 5970.97,2646.07 h60
  text "PTH" at 6632.97,2646.07 h60
  text "Round" at 6917.32,2646.07 h60
  text "488" at 5613.85,2496.61 h60
  text "13.00mil (0.330mm)" at 5970.97,2496.61 h60
  text "PTH" at 6632.97,2496.61 h60
  text "Round" at 6917.32,2496.61 h60
  text "16" at 5613.85,2347.15 h60
  text "15.75mil (0.400mm)" at 5970.97,2347.15 h60
  text "PTH" at 6632.97,2347.15 h60
  text "Round" at 6917.32,2347.15 h60
  text "1" at 5613.85,2197.69 h60
  text "27.56mil (0.700mm)" at 5970.97,2197.69 h60
  text "PTH" at 6632.97,2197.69 h60
  text "Round" at 6917.32,2197.69 h60
  text "2" at 5613.85,2048.23 h60
  text "28.00mil (0.711mm)" at 5970.97,2048.23 h60
  text "PTH" at 6632.97,2048.23 h60
  text "Round" at 6917.32,2048.23 h60
  text "8" at 5613.85,1898.77 h60
  text "33.46mil (0.850mm)" at 5970.97,1898.77 h60
  text "PTH" at 6632.97,1898.77 h60
  text "Round" at 6917.32,1898.77 h60
  text "41" at 5613.85,1749.32 h60
  text "35.43mil (0.900mm)" at 5970.97,1749.32 h60
  text "PTH" at 6632.97,1749.32 h60
  text "Round" at 6917.32,1749.32 h60
  text "4" at 5613.85,1599.86 h60
  text "43.31mil (1.100mm)" at 5970.97,1599.86 h60
  text "PTH" at 6632.97,1599.86 h60
  text "Round" at 6917.32,1599.86 h60
  text "10" at 5613.85,1450.4 h60
  text "66.93mil (1.700mm)" at 5970.97,1450.4 h60
  text "PTH" at 6632.97,1450.4 h60
  text "Round" at 6917.32,1450.4 h60
  text "2" at 5613.85,1300.94 h60
  text "70.87mil (1.800mm)" at 5970.97,1300.94 h60
  text "PTH" at 6632.97,1300.94 h60
  text "Round" at 6917.32,1300.94 h60
  text "4" at 5613.85,1151.48 h60
  text "125.98mil (3.200mm)" at 5970.97,1151.48 h60
  text "PTH" at 6632.97,1151.48 h60
  text "Round" at 6917.32,1151.48 h60
  text "616 Total" at 5613.85,1002.02 h60
  text ".Layer_Name" at 295.35,-1258.89 h60

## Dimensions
-0.65,-325.39 to 999.35,-325.39 on M2 Board Dimensions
